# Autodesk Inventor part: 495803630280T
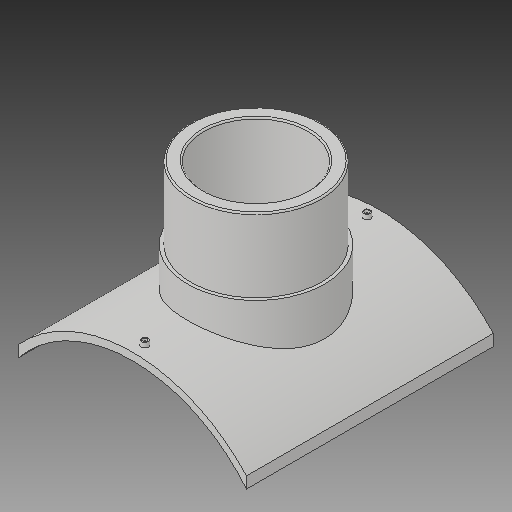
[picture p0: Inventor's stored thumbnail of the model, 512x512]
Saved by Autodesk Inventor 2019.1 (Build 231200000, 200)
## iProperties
Created: 2017-10
Part Number: 495803630280T
Material: Generic
Description: PLASSON BRANCH SADDLE  630x280
Document SubType Name: Modeling
Designer: KIM
Mass: 2754.05 g
Surface Area: 3037.44 cm^2
Volume: 2754.05 cm^3
Density: 1 g/cm^3
Appearance: Default
Author: KIM
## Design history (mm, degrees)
derived "495803.ipt"
feature "Solid1::495803.ipt"
tag "TaggingFeature1"
body "Solid1"
other parameters: "d1" = 16, "d2" = 489, "d4" = 0, "d12" = 340.6, "d13" = 14, "d14" = 238.5, "d16" = 5 deg, "d18" = 4, "d19" = 14, "d20" = 0, "d21" = 3, "d22" = 0, "d23" = 556, "d24" = 294, "d25" = 16, "d26" = 224, "d28" = 0, "d29" = 9.6, "d31" = 0, "d32" = 112.5, "d33" = 0, "d34" = 6.3, "d37" = 157.5, "d38" = 0, "d39" = 3.15, "B_" = 489, "H_" = 225, "x_" = 16, "D_" = 16
